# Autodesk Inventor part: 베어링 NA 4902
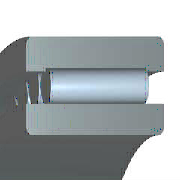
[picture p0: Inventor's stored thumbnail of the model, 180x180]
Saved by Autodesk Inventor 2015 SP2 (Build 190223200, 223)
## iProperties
IsCustomPart: 0
Manager: KYOUNG IL JANG
Company: 한국ATC센터
Created: 2009-02
Part Number: 베어링 NA 4902
Material: Steel, Mild
Description: 니들 롤러 베어링 - 경계 치수 및 공차
Document SubType Name: Modeling
Standard: KS B 2029
Standards Organization: KS
Language: ko-KR
Size Designation: NA 4902 - 15 x 28 x 13
Categories: <MemberInstance><Categories><Category DisplayName="샤프트 부품" InternalName="7f7aeb1f-a693-4053-b835-cee3144e0d98" Mnemonic="SHFT"><Category DisplayName="베어링" Inter
Density: 1 g/cm^3
Checked By: KYOUNG IL JANG
Vendor: CBT Solutions
Designer: KYOUNG IL JANG
Appearance: _시험-파란색 크롬
Author: KYOUNG IL JANG
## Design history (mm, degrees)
sketch "스케치"
  geometry: L1 (1.857, 11.5)-(11.143, 11.5); L2 (11.143, 11.5)-(11.143, 10); L3 (13, 10)-(0, 10); L4 (1.857, 10)-(1.857, 11.5); L5 (1.857, 10.75)-(11.143, 10.75); L6 (6.5, 10.75)-(6.5, 10); L7 (0, 7.5)-(13, 7.5); L8 (0, 14)-(13, 14); L9 (13, 7.5)-(13, 10); L10 (13, 11.35)-(13, 14); L11 (1.857, 11.35)-(0, 11.35); L12 (11.143, 11.35)-(13, 11.35); L13 (-6, 0)-(36, 0) reference; L14 (0, -1.9)-(0, 14.9) reference
  constraints: 24 end point, 8 point on line, 3 midpoint, 3 parallel, 3 perpendicular, 2 symmetric about line, 1 horizontal, 1 other
  dimensions: "d6" = 15 diameter of L7 L13 (= WD); "d7" = 20 diameter of L3 L13 (= KID1); "d8" = 28 diameter of L8 L13 (= BD); "d9" = 21.5 diameter of L6.start L13 (= 0.5 x WD + 0.5 x BD); "d10" = 22.7 diameter of L12 L13 (= 0.9 x BD + 0.9 x WD - 0.8 x KID1); "d11" = 23 diameter of L1 L13 (= BD + WD - KID1); "d12" = 1.85714 distance between parallel lines of L14 L4 (= 0.142857 x KB); "d13" = 13 distance between parallel lines of L14 L9 (= KB); "d14" = 11.14286 distance between parallel lines of L14 L2 (= 0.857143 x KB)
revolve "본체" stored, may be unused: angle "d17" = 90 deg
revolve "롤러" stored, may be unused: angle "d18" = 90 deg
body "Solid1"
fillet "모깎기1" dims "d0" = 0.3 (= KRS)
pattern_circular "IDS_ARRAYROLLER[SIMPL:T]" dims angle "d2" = 360 deg
other parameters: "WD" = 15 [user parameter; used in 6 equation terms], "BD" = 28 [user parameter; used in 6 equation terms], "KB" = 13 [user parameter; used in 3 equation terms], "KID1" = 20 [user parameter; used in 4 equation terms], "KRS" = 0.3 [user parameter; used in 1 equation term], "d3" = 0, "d4" = 0, "d5" = 0, "d15" = 0, "d16" = 0, "BC0" = 1.37e+07 [user parameter], "WR" = 7.5 (= 0.5 x WD) [user parameter], "BBA" = 0 [user parameter], "BC" = 1.02e+07 [user parameter], "BR" = 14 (= 0.5 x BD) [user parameter]
